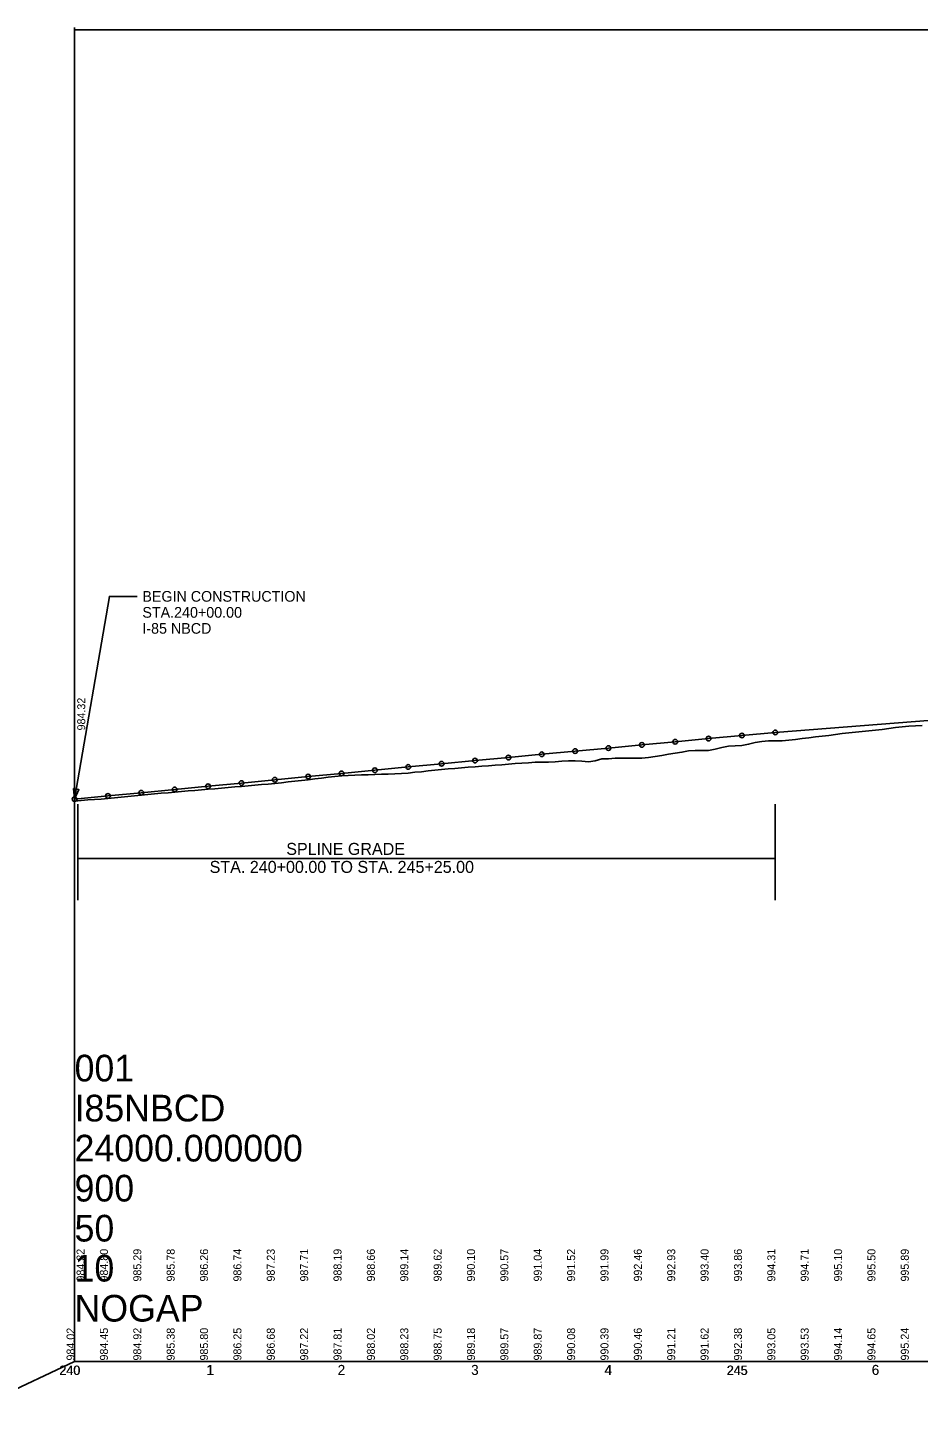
# Model space of a CAD drawing. Extents: x 1608361 to 16979326, y 1092015 to 12565288.
# Drawn here: x 16972950 to 16973618, y 12564256 to 12565288 of the extents above; entities that cross this region are included whole.
import ezdxf

# ---------------------------------------------------------------- set-up
doc = ezdxf.new("R2010")
doc.units = 0
for name, color, linetype in [('Default', 7, 'Continuous'), ('RD_EX_BldgApp_txCode', 7, 'Continuous'), ('RD_EX_H2O', 7, 'Continuous'), ('RD_EX_RW_Approx', 7, 'Continuous'), ('RD_EX_SU_Water', 7, 'Continuous'), ('RD_EX_UT', 7, 'Continuous'), ('RD_HC_Data_Tic_Rel', 7, 'Continuous'), ('RD_HC_TX_Rel_Sta50', 7, 'Continuous'), ('RD_PD_Final_TX', 7, 'Continuous'), ('RD_SHT_Snap', 7, 'Continuous'), ('TEXT2', 7, 'Continuous')]:
    doc.layers.add(name, color=color, linetype=linetype)

msp = doc.modelspace()

# ---------------------------------------------------------------- linework, layer by layer
at = {"layer": 'Default'}
msp.add_lwpolyline([(16972985.6, 12564287.8), (16974485.6, 12564287.8), (16974485.6, 12565286), (16972985.6, 12565286)], close=True, dxfattribs=at)
at = {"layer": 'RD_EX_BldgApp_txCode'}
for p, q in [((16972988.1, 12564633.8), (16972988.1, 12564705.6)), ((16973510.6, 12564633.8), (16973510.6, 12564705.6)), ((16972988.1, 12564665), (16973510.6, 12564665))]:
    msp.add_line(p, q, dxfattribs=at)
at = {"layer": 'RD_EX_H2O'}
for points in [[(16973485.6, 12564749.7), (16973490.6, 12564750.6), (16973495.6, 12564751.8), (16973500.6, 12564752.6), (16973505.6, 12564753.2), (16973510.6, 12564753), (16973515.6, 12564753.2), (16973520.6, 12564753.7), (16973525.6, 12564754.2), (16973530.6, 12564754.8), (16973535.6, 12564755.4), (16973540.6, 12564756.1), (16973545.6, 12564756.7), (16973550.6, 12564757.2), (16973555.6, 12564757.8), (16973560.6, 12564758.5), (16973565.6, 12564759.1), (16973570.6, 12564759.7), (16973575.6, 12564760.1), (16973580.6, 12564760.6), (16973585.6, 12564761), (16973590.6, 12564761.6), (16973595.6, 12564762.3), (16973600.6, 12564763.1), (16973605.6, 12564763.6), (16973610.6, 12564764), (16973615.6, 12564764.4), (16973620.6, 12564764.7)], [(16972985.6, 12564707.9), (16972990.6, 12564708.4), (16972995.6, 12564708.8), (16973000.6, 12564709.1), (16973005.6, 12564709.5), (16973010.6, 12564710), (16973015.6, 12564710.5), (16973020.6, 12564711), (16973025.6, 12564711.4), (16973030.6, 12564711.9), (16973035.6, 12564712.4), (16973040.6, 12564713), (16973045.6, 12564713.4), (16973050.6, 12564713.8), (16973055.6, 12564714.2), (16973060.6, 12564714.7), (16973065.6, 12564715.2), (16973070.6, 12564715.6), (16973075.6, 12564716), (16973080.6, 12564716.4), (16973085.6, 12564716.8), (16973090.6, 12564717.2), (16973095.6, 12564717.7), (16973100.6, 12564718.1), (16973105.6, 12564718.6), (16973110.6, 12564719), (16973115.6, 12564719.4), (16973120.6, 12564719.9), (16973125.6, 12564720.3), (16973130.6, 12564720.7), (16973135.6, 12564721.2), (16973140.6, 12564721.7), (16973145.6, 12564722.3), (16973150.6, 12564722.8), (16973155.6, 12564723.3), (16973160.6, 12564723.9), (16973165.6, 12564724.6), (16973170.6, 12564725.2), (16973175.6, 12564725.9), (16973180.6, 12564726.5), (16973185.6, 12564726.9), (16973190.6, 12564727.1), (16973195.6, 12564727.4), (16973200.6, 12564727.5), (16973205.6, 12564727.6), (16973210.6, 12564727.9), (16973215.6, 12564728.1), (16973220.6, 12564728.2), (16973225.6, 12564728.4), (16973230.6, 12564728.5), (16973235.6, 12564728.9), (16973240.6, 12564729.5), (16973245.6, 12564729.9), (16973250.6, 12564730.5), (16973255.6, 12564731), (16973260.6, 12564731.5), (16973265.6, 12564732), (16973270.6, 12564732.3), (16973275.6, 12564732.9), (16973280.6, 12564733.3), (16973285.6, 12564733.7), (16973290.6, 12564734.1), (16973295.6, 12564734.4), (16973300.6, 12564734.8), (16973305.6, 12564735.2), (16973310.6, 12564735.6), (16973315.6, 12564736), (16973320.6, 12564736.4), (16973325.6, 12564736.7), (16973330.6, 12564737.1), (16973335.6, 12564737.1), (16973340.6, 12564737.1), (16973345.6, 12564737.3), (16973350.6, 12564737.8), (16973355.6, 12564738.2), (16973360.6, 12564738.2), (16973365.6, 12564737.8), (16973370.6, 12564737.4), (16973375.6, 12564738.2), (16973380.6, 12564739.5), (16973385.6, 12564739.7), (16973390.6, 12564740), (16973395.6, 12564740.1), (16973400.6, 12564740.2), (16973405.6, 12564740.2), (16973410.6, 12564740.1), (16973415.6, 12564740.6), (16973420.6, 12564741.4), (16973425.6, 12564742.2), (16973430.6, 12564743), (16973435.6, 12564743.8), (16973440.6, 12564744.6), (16973445.6, 12564745.5), (16973450.6, 12564745.9), (16973455.6, 12564745.9), (16973460.6, 12564745.9), (16973465.6, 12564746.9), (16973470.6, 12564748), (16973475.6, 12564749), (16973480.6, 12564749.3), (16973485.6, 12564749.7)]]:
    msp.add_lwpolyline(points, dxfattribs=at)
at = {"layer": 'RD_EX_RW_Approx'}
for centre in [(16973510.6, 12564759.4), (16973385.6, 12564747.7), (16973410.6, 12564750.1), (16973435.6, 12564752.4), (16973460.6, 12564754.8), (16973485.6, 12564757.1), (16973285.6, 12564738.3), (16973310.6, 12564740.6), (16973335.6, 12564743), (16973360.6, 12564745.4), (16973160.6, 12564726.3), (16973185.6, 12564728.7), (16973210.6, 12564731.1), (16973235.6, 12564733.5), (16973260.6, 12564735.9), (16973060.6, 12564716.7), (16973085.6, 12564719.1), (16973110.6, 12564721.5), (16973135.6, 12564723.9), (16972985.6, 12564709.4), (16973010.6, 12564711.8), (16973035.6, 12564714.2)]:
    msp.add_circle(centre, 1.75, dxfattribs=at)
at = {"layer": 'RD_EX_UT'}
for q in [(16972985.6, 12565287.8), (16978789.9, 12564287.8), (16972985.6, 12564287.8)]:
    msp.add_line((16972985.6, 12564287.8), q, dxfattribs=at)
at = {"layer": 'RD_HC_Data_Tic_Rel'}
msp.add_line((16972985.6, 12564287.8), (16970722.5, 12563223.5), dxfattribs=at)
at = {"layer": 'RD_HC_TX_Rel_Sta50'}
for p, q in [((16973510.6, 12564759.4), (16973805.6, 12564782.7)), ((16973485.6, 12564757.1), (16973510.6, 12564759.4)), ((16973385.6, 12564747.7), (16973410.6, 12564750.1)), ((16973410.6, 12564750.1), (16973435.6, 12564752.4)), ((16973435.6, 12564752.4), (16973460.6, 12564754.8)), ((16973460.6, 12564754.8), (16973485.6, 12564757.1)), ((16973285.6, 12564738.3), (16973310.6, 12564740.6)), ((16973310.6, 12564740.6), (16973335.6, 12564743)), ((16973335.6, 12564743), (16973360.6, 12564745.4)), ((16973360.6, 12564745.4), (16973385.6, 12564747.7)), ((16973160.6, 12564726.3), (16973185.6, 12564728.7)), ((16973185.6, 12564728.7), (16973210.6, 12564731.1)), ((16973210.6, 12564731.1), (16973235.6, 12564733.5)), ((16973235.6, 12564733.5), (16973260.6, 12564735.9)), ((16973260.6, 12564735.9), (16973285.6, 12564738.3)), ((16973060.6, 12564716.7), (16973085.6, 12564719.1)), ((16973085.6, 12564719.1), (16973110.6, 12564721.5)), ((16973110.6, 12564721.5), (16973135.6, 12564723.9)), ((16973135.6, 12564723.9), (16973160.6, 12564726.3)), ((16972985.6, 12564709.4), (16973010.6, 12564711.8)), ((16973010.6, 12564711.8), (16973035.6, 12564714.2)), ((16973035.6, 12564714.2), (16973060.6, 12564716.7))]:
    msp.add_line(p, q, dxfattribs=at)
at = {"layer": 'RD_SHT_Snap'}
msp.add_lwpolyline([(16973032.4, 12564861.4), (16973011.7, 12564861.4), (16972985.6, 12564709.4)], dxfattribs=at)
msp.add_lwpolyline([(16972984.8, 12564717.3), (16972985.6, 12564709.4), (16972988.9, 12564716.6)], close=True, dxfattribs=at)

# ---------------------------------------------------------------- texts
at = {"layer": 'RD_EX_BldgApp_txCode'}
for s, p in [('SPLINE GRADE', (16973144.2, 12564667.6)), ('STA. 240+00.00 TO STA. 245+25.00', (16973086.8, 12564654.1))]:
    msp.add_text(s, height=9, dxfattribs=at).set_placement(p)
at = {"layer": 'RD_EX_RW_Approx'}
msp.add_text('984.32', height=6, rotation=90, dxfattribs=at).set_placement((16972993.6, 12564760.9))
at = {"layer": 'RD_EX_SU_Water'}
for s, p in [('984.32', (16972993.1, 12564347.8)), ('984.80', (16973010.6, 12564347.8)), ('985.29', (16973035.6, 12564347.8)), ('985.78', (16973060.6, 12564347.8)), ('986.26', (16973085.6, 12564347.8)), ('986.74', (16973110.6, 12564347.8)), ('987.23', (16973135.6, 12564347.8)), ('987.71', (16973160.6, 12564347.8)), ('988.19', (16973185.6, 12564347.8)), ('988.66', (16973210.6, 12564347.8)), ('989.14', (16973235.6, 12564347.8)), ('989.62', (16973260.6, 12564347.8)), ('990.10', (16973285.6, 12564347.8)), ('990.57', (16973310.6, 12564347.8)), ('991.04', (16973335.6, 12564347.8)), ('991.52', (16973360.6, 12564347.8)), ('991.99', (16973385.6, 12564347.8)), ('992.46', (16973410.6, 12564347.8)), ('992.93', (16973435.6, 12564347.8)), ('993.40', (16973460.6, 12564347.8)), ('993.86', (16973485.6, 12564347.8)), ('994.31', (16973510.6, 12564347.8)), ('994.71', (16973535.6, 12564347.8)), ('995.10', (16973560.6, 12564347.8)), ('995.50', (16973585.6, 12564347.8)), ('995.89', (16973610.6, 12564347.8))]:
    msp.add_text(s, height=6, rotation=90, dxfattribs=at).set_placement(p)
at = {"layer": 'RD_EX_UT'}
for s, p in [('001', (16972985.6, 12564497.8)), ('I85NBCD', (16972985.6, 12564467.8)), ('24000.000000', (16972985.6, 12564437.8)), ('900', (16972985.6, 12564407.8)), ('50', (16972985.6, 12564377.8)), ('10', (16972985.6, 12564347.8)), ('NOGAP', (16972985.6, 12564317.8))]:
    msp.add_text(s, height=20, dxfattribs=at).set_placement(p)
at = {"layer": 'RD_PD_Final_TX'}
for s, height, p in [('240', 7, (16972974.1, 12564277.8)), ('240', 7, (16972974.4, 12564277.8)), ('1', 7.5, (16973084.2, 12564277.8)), ('1', 7.5, (16973084.6, 12564277.8)), ('2', 7.5, (16973182.7, 12564277.8)), ('2', 7.5, (16973182.8, 12564277.8)), ('3', 7.5, (16973282.7, 12564277.8)), ('3', 7.5, (16973282.8, 12564277.8)), ('4', 7.5, (16973382.5, 12564277.8)), ('4', 7.5, (16973382.8, 12564277.8)), ('245', 7, (16973474.1, 12564277.8)), ('245', 7, (16973474.4, 12564277.8)), ('6', 7.5, (16973582.8, 12564277.8)), ('6', 7.5, (16973582.9, 12564277.8))]:
    msp.add_text(s, height=height, dxfattribs=at).set_placement(p)
at = {"layer": 'RD_SHT_Snap'}
for s, p in [('BEGIN CONSTRUCTION', (16973036.4, 12564857.4)), ('STA.240+00.00 ', (16973036.4, 12564845.4)), ('I-85 NBCD', (16973036.4, 12564833.4))]:
    msp.add_text(s, height=8, dxfattribs=at).set_placement(p)
at = {"layer": 'TEXT2'}
for s, p in [('984.02', (16972985.6, 12564288.6)), ('984.45', (16973010.6, 12564288.6)), ('984.92', (16973035.6, 12564288.6)), ('985.38', (16973060.6, 12564288.6)), ('985.80', (16973085.6, 12564288.6)), ('986.25', (16973110.6, 12564288.6)), ('986.68', (16973135.6, 12564288.6)), ('987.22', (16973160.6, 12564288.6)), ('987.81', (16973185.6, 12564288.6)), ('988.02', (16973210.6, 12564288.6)), ('988.23', (16973235.6, 12564288.6)), ('988.75', (16973260.6, 12564288.6)), ('989.18', (16973285.6, 12564288.6)), ('989.57', (16973310.6, 12564288.6)), ('989.87', (16973335.6, 12564288.6)), ('990.08', (16973360.6, 12564288.6)), ('990.39', (16973385.6, 12564288.6)), ('990.46', (16973410.6, 12564288.6)), ('991.21', (16973435.6, 12564288.6)), ('991.62', (16973460.6, 12564288.6)), ('992.38', (16973485.6, 12564288.6)), ('993.05', (16973510.6, 12564288.6)), ('993.53', (16973535.6, 12564288.6)), ('994.14', (16973560.6, 12564288.6)), ('994.65', (16973585.6, 12564288.6)), ('995.24', (16973610.6, 12564288.6))]:
    msp.add_text(s, height=6, rotation=90, dxfattribs=at).set_placement(p)

doc.saveas('drawing.dxf')
